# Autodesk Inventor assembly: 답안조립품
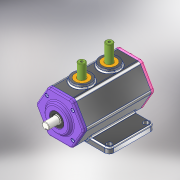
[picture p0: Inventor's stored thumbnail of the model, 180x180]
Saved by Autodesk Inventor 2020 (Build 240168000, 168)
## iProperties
Created: 2021-06
Part Number: 답안조립품
Document SubType Name: Assembly
Designer: MIRAE
Author: MIRAE
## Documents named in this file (11)
- C:\Users\MIRAE\Desktop\710606V1010\답안조립품.iam
- C:\Users\MIRAE\Desktop\710606V1010\본체.ipt
- C:\Users\MIRAE\Desktop\710606V1010\베어링 6203.ipt
- C:\Users\MIRAE\Desktop\710606V1010\앞커버.ipt
- C:\Users\MIRAE\Desktop\710606V1010\오일실.ipt
- C:\Users\MIRAE\Desktop\710606V1010\뒷커버.ipt
- C:\Users\MIRAE\Desktop\710606V1010\베어링 6302.ipt
- C:\Users\MIRAE\Desktop\710606V1010\편심축.ipt
- C:\Users\MIRAE\Desktop\710606V1010\슬라이더.ipt
- C:\Users\MIRAE\Desktop\710606V1010\부시.ipt
- C:\Users\MIRAE\Desktop\710606V1010\볼트 M4.ipt
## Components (10 placed, 3 different names)
1. 7-베어링 6203:1
2. 8-오일실:1
3. 9-M4-소켓머리:2
4. 9-M4-소켓머리:3
5. 9-M4-소켓머리:4
6. 9-M4-소켓머리:5
7. 9-M4-소켓머리:1
8. 9-M4-소켓머리:6
9. 9-M4-소켓머리:7
10. 9-M4-소켓머리:8
